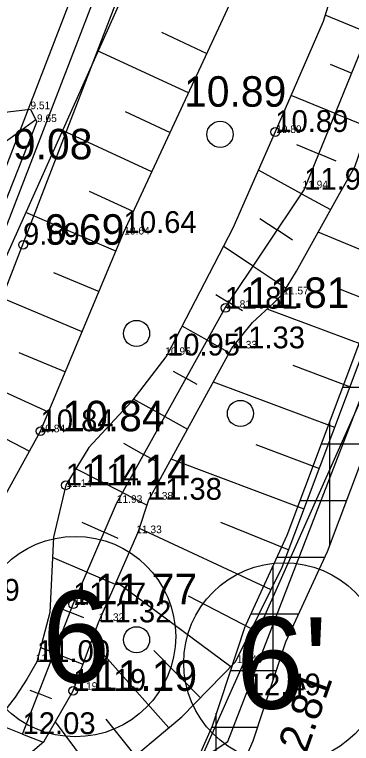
# Model space of a CAD drawing. Extents: x 433497 to 434382, y 6534486 to 6534993.
# Drawn here: x 434142.29 to 434157.72, y 6534787.09 to 6534820.55 of the extents above; entities that cross this region are included whole.
import ezdxf

# ---------------------------------------------------------------- set-up
doc = ezdxf.new("R2010")
doc.units = 0
for name, color, linetype in [('HALJASTUS', 7, 'Continuous'), ('Kaitsevöönd', 7, 'Continuous'), ('kataster', 7, 'Continuous'), ('KORGUS-EH2000', 7, 'Continuous'), ('MOOTKORG-EH2000', 7, 'Continuous'), ('PIIR', 7, 'Continuous'), ('RELJEEF', 7, 'Continuous'), ('TEE', 7, 'Continuous')]:
    doc.layers.add(name, color=color, linetype=linetype)

msp = doc.modelspace()

# ---------------------------------------------------------------- linework, layer by layer
at = {"layer": 'HALJASTUS'}
for centre in [(434151.702, 6534815.048), (434147.874, 6534805.908), (434152.639, 6534802.236), (434147.874, 6534791.847)]:
    msp.add_circle(centre, 0.6, dxfattribs=at)
at = {"layer": 'Kaitsevöönd'}
for p, q in [((434157.321, 6534803.439), (434159.458, 6534803.439)), ((434156.731, 6534796.172), (434156.731, 6534801.866)), ((434156.346, 6534800.839), (434158.482, 6534800.839)), ((434155.37, 6534798.239), (434157.506, 6534798.239)), ((434154.309, 6534795.639), (434156.509, 6534795.639)), ((434154.131, 6534789.966), (434154.131, 6534795.252)), ((434153.111, 6534793.039), (434155.312, 6534793.039)), ((434152.18, 6534790.439), (434154.287, 6534790.439)), ((434151.531, 6534783.359), (434151.531, 6534788.471)), ((434151.318, 6534787.839), (434153.428, 6534787.839))]:
    msp.add_line(p, q, dxfattribs=at)
for points in [[(434128.222, 6534730.093), (434132.174, 6534738.642), (434136.032, 6534747.247), (434138.365, 6534752.329), (434142.93, 6534762.753), (434145.458, 6534769.142), (434146.369, 6534771.613), (434148.646, 6534776.777), (434150.916, 6534781.958), (434153.219, 6534787.206), (434154.721, 6534791.754), (434156.628, 6534795.899), (434159.877, 6534804.556), (434163.808, 6534814.841), (434168.182, 6534825.411), (434171.941, 6534834.072), (434175.51, 6534841.483), (434180.59, 6534850.694), (434185.974, 6534861.252), (434188.694, 6534866.232), (434193.777, 6534875.182), (434200.729, 6534887.95), (434203.323, 6534892.681)], [(434198.974, 6534888.909), (434192.024, 6534876.146), (434186.943, 6534867.198), (434184.199, 6534862.173), (434178.816, 6534851.617), (434173.72, 6534842.375), (434170.114, 6534834.886), (434166.338, 6534826.183), (434161.945, 6534815.568), (434158.005, 6534805.262), (434154.768, 6534796.635), (434152.881, 6534792.54), (434152.839, 6534792.435), (434151.335, 6534787.878), (434149.085, 6534782.762), (434146.815, 6534777.582), (434144.503, 6534772.334), (434143.585, 6534769.845), (434141.077, 6534763.506), (434136.537, 6534753.14), (434134.209, 6534748.069), (434130.352, 6534739.465)]]:
    msp.add_lwpolyline(points, dxfattribs=at)
at = {"layer": 'kataster'}
msp.add_lwpolyline([(434117.185, 6534708.296), (434124.427, 6534725.502), (434148.55, 6534781.242), (434178.983, 6534849.691), (434202.394, 6534892.23)], dxfattribs=at)
at = {"layer": 'KORGUS-EH2000'}
for centre in [(434154.235, 6534815.156), (434142.672, 6534809.98), (434151.95, 6534807.08), (434143.477, 6534801.419), (434144.636, 6534798.937), (434144.967, 6534793.475), (434144.967, 6534789.503)]:
    msp.add_circle(centre, 0.2, dxfattribs=at)
at = {"layer": 'PIIR'}
for points in [[(434137.312, 6534801.699), (434156.44, 6534851.34), (434184.392, 6534902.877)], [(434138.342, 6534801.592), (434157.35, 6534850.92), (434185.271, 6534902.4)], [(434138.358, 6534798.853), (434158.26, 6534850.5), (434186.15, 6534901.923)]]:
    msp.add_lwpolyline(points, dxfattribs=at)
for centre in [(434145.069, 6534791.991), (434154.637, 6534790.783)]:
    msp.add_circle(centre, 4.6, dxfattribs=at)
at = {"layer": 'RELJEEF'}
for p, q in [((434158.491, 6534819.712), (434156.522, 6534820.513)), ((434149.018, 6534819.732), (434151.104, 6534818.766)), ((434150.263, 6534816.951), (434146.116, 6534818.873)), ((434156.747, 6534818.262), (434157.737, 6534817.859)), ((434156.983, 6534816.007), (434154.961, 6534816.83)), ((434147.361, 6534816.092), (434149.422, 6534815.136)), ((434156.983, 6534816.007), (434158.414, 6534815.424)), ((434143.26, 6534815.713), (434141.911, 6534814.734)), ((434148.581, 6534813.322), (434144.483, 6534815.221)), ((434155.201, 6534814.586), (434156.229, 6534814.154)), ((434157.03, 6534813.818), (434156.229, 6534814.154)), ((434155.436, 6534812.323), (434153.461, 6534813.397)), ((434145.696, 6534812.433), (434147.74, 6534811.507)), ((434155.436, 6534812.323), (434156.772, 6534811.595)), ((434146.931, 6534809.679), (434142.8, 6534811.456)), ((434153.526, 6534811.192), (434154.326, 6534810.659)), ((434155.029, 6534810.19), (434154.326, 6534810.659)), ((434159.832, 6534809.055), (434156.198, 6534810.56)), ((434153.217, 6534808.995), (434151.858, 6534809.9)), ((434144.062, 6534808.711), (434146.159, 6534807.833)), ((434153.217, 6534808.995), (434154.732, 6534807.984)), ((434145.388, 6534805.988), (434141.148, 6534807.761)), ((434151.51, 6534807.701), (434152.107, 6534807.331)), ((434157.128, 6534807.969), (434159.073, 6534807.205)), ((434152.726, 6534806.947), (434152.107, 6534807.331)), ((434158.369, 6534805.333), (434153.858, 6534807.028)), ((434151.112, 6534805.597), (434149.967, 6534806.243)), ((434151.112, 6534805.597), (434152.136, 6534805.019)), ((434142.474, 6534805.039), (434144.616, 6534804.143)), ((434155.039, 6534804.448), (434157.665, 6534803.461)), ((434143.845, 6534802.298), (434139.569, 6534804.231)), ((434149.554, 6534804.175), (434150.141, 6534803.848)), ((434150.66, 6534803.56), (434150.141, 6534803.848)), ((434156.962, 6534801.588), (434151.402, 6534803.679)), ((434149.17, 6534802.1), (434147.733, 6534802.898)), ((434149.17, 6534802.1), (434150.218, 6534801.518)), ((434140.914, 6534801.571), (434142.97, 6534800.503)), ((434147.272, 6534800.866), (434148.199, 6534800.352)), ((434153.345, 6534800.811), (434156.258, 6534799.716)), ((434148.728, 6534800.057), (434148.199, 6534800.352)), ((434155.554, 6534797.844), (434149.461, 6534800.135)), ((434147.227, 6534798.603), (434145.092, 6534799.689)), ((434147.227, 6534798.603), (434148.36, 6534798.027)), ((434145.363, 6534797.247), (434146.388, 6534796.79)), ((434151.717, 6534797.252), (434154.851, 6534795.972)), ((434147.04, 6534796.5), (434146.388, 6534796.79)), ((434154.044, 6534794.145), (434148.004, 6534796.959)), ((434145.6, 6534794.952), (434144.02, 6534795.623)), ((434145.6, 6534794.952), (434146.897, 6534794.401)), ((434152.202, 6534790.609), (434146.945, 6534794.51)), ((434150.246, 6534793.868), (434153.162, 6534792.349)), ((434144.374, 6534793.291), (434144.824, 6534793.109)), ((434145.464, 6534792.85), (434144.824, 6534793.109)), ((434149.355, 6534787.805), (434145.811, 6534791.795)), ((434144.099, 6534791.245), (434143.484, 6534791.484)), ((434148.661, 6534791.355), (434150.806, 6534789.177)), ((434144.099, 6534791.245), (434145.419, 6534790.732)), ((434142.991, 6534789.53), (434143.375, 6534789.381)), ((434143.997, 6534789.139), (434143.375, 6534789.381)), ((434142.65, 6534787.517), (434141.37, 6534788.014)), ((434146.249, 6534785.287), (434144.153, 6534788.08)), ((434146.461, 6534788.199), (434147.819, 6534786.524)), ((434142.65, 6534787.517), (434143.598, 6534787.148))]:
    msp.add_line(p, q, dxfattribs=at)
for points in [[(434116.003, 6534779.573), (434118.33, 6534779.008), (434124.552, 6534778.351), (434128.388, 6534778.248), (434131.064, 6534778.414), (434134.99, 6534779.596), (434139.415, 6534780.978), (434142.65, 6534782.717), (434146.846, 6534785.714), (434149.957, 6534788.306), (434152.414, 6534790.827), (434154.555, 6534795.185), (434159.2, 6534807.543), (434167.641, 6534827.734), (434175.75, 6534844.947), (434185.846, 6534863.98), (434196.935, 6534884.171), (434200.713, 6534891.388)], [(434116.003, 6534779.573), (434118.33, 6534779.008), (434124.552, 6534778.351), (434128.388, 6534778.248), (434131.064, 6534778.414), (434134.99, 6534779.596), (434139.415, 6534780.978), (434142.65, 6534782.717), (434146.846, 6534785.714), (434149.957, 6534788.306), (434152.414, 6534790.827), (434154.555, 6534795.185), (434159.2, 6534807.543), (434167.641, 6534827.734), (434175.75, 6534844.947), (434185.846, 6534863.98), (434196.935, 6534884.171)], [(434113.19, 6534781.228), (434119.148, 6534781.228), (434129.078, 6534780.4), (434131.196, 6534780.65), (434133.547, 6534781.228), (434134.6, 6534782.717), (434135.868, 6534785.182), (434136.526, 6534787.186), (434139.174, 6534793.64), (434143.477, 6534801.419), (434147.284, 6534810.522), (434153.573, 6534824.093), (434156.717, 6534837.003), (434157.71, 6534847.595)], [(434158.687, 6534827.511), (434156.433, 6534820.225), (434154.235, 6534815.156), (434152.292, 6534810.738), (434149.27, 6534804.895), (434147.653, 6534802.794), (434145.688, 6534800.671), (434144.636, 6534798.937), (434144.063, 6534796.557), (434143.906, 6534793.097), (434143.312, 6534790.827), (434142.844, 6534790.044), (434142.307, 6534789.219), (434140.931, 6534787.45), (434140.664, 6534786.855)], [(434142.65, 6534787.517), (434144.967, 6534793.475), (434146.953, 6534798.109), (434151.918, 6534807.046), (434155.559, 6534812.508), (434161.352, 6534826.741)], [(434142.766, 6534786.441), (434143.643, 6534787.186), (434144.967, 6534789.503), (434146.125, 6534792.647), (434147.946, 6534796.785), (434148.442, 6534798.275), (434152.249, 6534805.226), (434153.183, 6534806.417), (434154.153, 6534807.295), (434154.566, 6534807.708), (434155.201, 6534808.763), (434157.193, 6534812.353), (434157.874, 6534813.559), (434158.207, 6534814.494), (434158.425, 6534815.472), (434158.372, 6534816.599), (434158.538, 6534817.308), (434162.146, 6534824.674)], [(434138.05, 6534800.835), (434147.118, 6534821.114), (434146.988, 6534822.533)], [(434108.205, 6534793.713), (434116.351, 6534796.246), (434120.106, 6534798.748), (434129.148, 6534799.622), (434131.664, 6534803.782), (434132.866, 6534809.14), (434135.095, 6534810.674), (434136.304, 6534808.284), (434137.928, 6534815.607), (434143.009, 6534816.202), (434143.311, 6534815.613)], [(434109.687, 6534786.673), (434112.222, 6534786.179), (434118.757, 6534788.35), (434129.51, 6534792.559), (434134.019, 6534795.71), (434135.253, 6534797.374), (434140.289, 6534808.003), (434143.311, 6534815.613)]]:
    msp.add_lwpolyline(points, dxfattribs=at)
at = {"layer": 'TEE'}
msp.add_lwpolyline([(434144.327, 6534780.781), (434148.542, 6534784.856), (434152.063, 6534787.177), (434164.597, 6534819.637), (434164.618, 6534819.688), (434164.64, 6534819.741), (434164.664, 6534819.795), (434169.822, 6534831.305), (434169.85, 6534831.366), (434169.88, 6534831.428), (434169.913, 6534831.492), (434175.016, 6534841.167), (434175.017, 6534841.169), (434175.019, 6534841.173), (434188.094, 6534865.834), (434188.111, 6534865.865), (434188.13, 6534865.899), (434188.15, 6534865.935), (434194.097, 6534876.248), (434200.82, 6534889.301), (434200.841, 6534889.341), (434200.864, 6534889.384), (434200.889, 6534889.428), (434202.717, 6534892.621)], dxfattribs=at)

# ---------------------------------------------------------------- texts
at = {"layer": 'KORGUS-EH2000'}
for s, p in [('10.89', (434150.054, 6534816.316)), ('9.08', (434142.209, 6534813.9)), ('9.69', (434143.672, 6534809.98)), ('11.81', (434152.95, 6534807.08)), ('10.84', (434144.477, 6534801.419)), ('11.14', (434145.636, 6534798.937)), ('11.77', (434145.967, 6534793.475)), ('11.19', (434145.967, 6534789.503))]:
    msp.add_text(s, height=1.4, dxfattribs=at).set_placement(p)
msp.add_text('12.81', height=1.4, rotation=70.508, dxfattribs=at).set_placement((434155.305, 6534785.607))
at = {"layer": 'MOOTKORG-EH2000'}
for s, height, p in [('9.51', 0.35, (434143.009, 6534816.202)), ('10.89', 1, (434154.235, 6534815.156)), ('9.65', 0.35, (434143.311, 6534815.613)), ('10.89', 0.35, (434154.27, 6534815.11)), ('11.94', 1, (434155.559, 6534812.508)), ('11.94', 0.35, (434155.48, 6534812.57)), ('10.64', 1, (434147.284, 6534810.522)), ('9.69', 1, (434142.672, 6534809.98)), ('10.64', 0.35, (434147.31, 6534810.45)), ('11.81', 1, (434151.918, 6534807.046)), ('11.57', 0.35, (434154.6, 6534807.7)), ('11.81', 0.35, (434151.95, 6534807.08)), ('11.33', 1, (434152.249, 6534805.226)), ('10.95', 1, (434149.27, 6534804.895)), ('11.33', 0.35, (434152.23, 6534805.22)), ('10.95', 0.35, (434149.19, 6534804.92)), ('10.84', 1, (434143.477, 6534801.419)), ('10.84', 0.35, (434143.43, 6534801.37)), ('11.14', 1, (434144.636, 6534798.937)), ('11.14', 0.35, (434144.66, 6534798.86)), ('11.38', 1, (434148.442, 6534798.275)), ('11.93', 0.35, (434146.97, 6534798.13)), ('11.38', 0.35, (434148.38, 6534798.28)), ('11.33', 0.35, (434147.86, 6534796.74)), ('10.89', 1, (434139.174, 6534793.64)), ('11.77', 1, (434144.967, 6534793.475)), ('11.77', 0.35, (434145.02, 6534793.44)), ('11.32', 1, (434146.125, 6534792.647)), ('11.32', 0.35, (434146.14, 6534792.71)), ('11.00', 1, (434143.312, 6534790.827)), ('11.00', 0.35, (434143.25, 6534790.83)), ('12.49', 0.35, (434152.47, 6534790.78)), ('11.19', 1, (434144.967, 6534789.503)), ('12.49', 1, (434152.974, 6534789.297)), ('11.19', 0.35, (434144.91, 6534789.55)), ('12.03', 1, (434142.65, 6534787.517))]:
    msp.add_text(s, height=height, dxfattribs=at).set_placement(p)
at = {"layer": 'PIIR'}
for s, p in [('6', (434143.542, 6534789.891)), ("6'", (434152.436, 6534788.683))]:
    msp.add_text(s, height=4.2, dxfattribs=at).set_placement(p)

doc.saveas('drawing.dxf')
